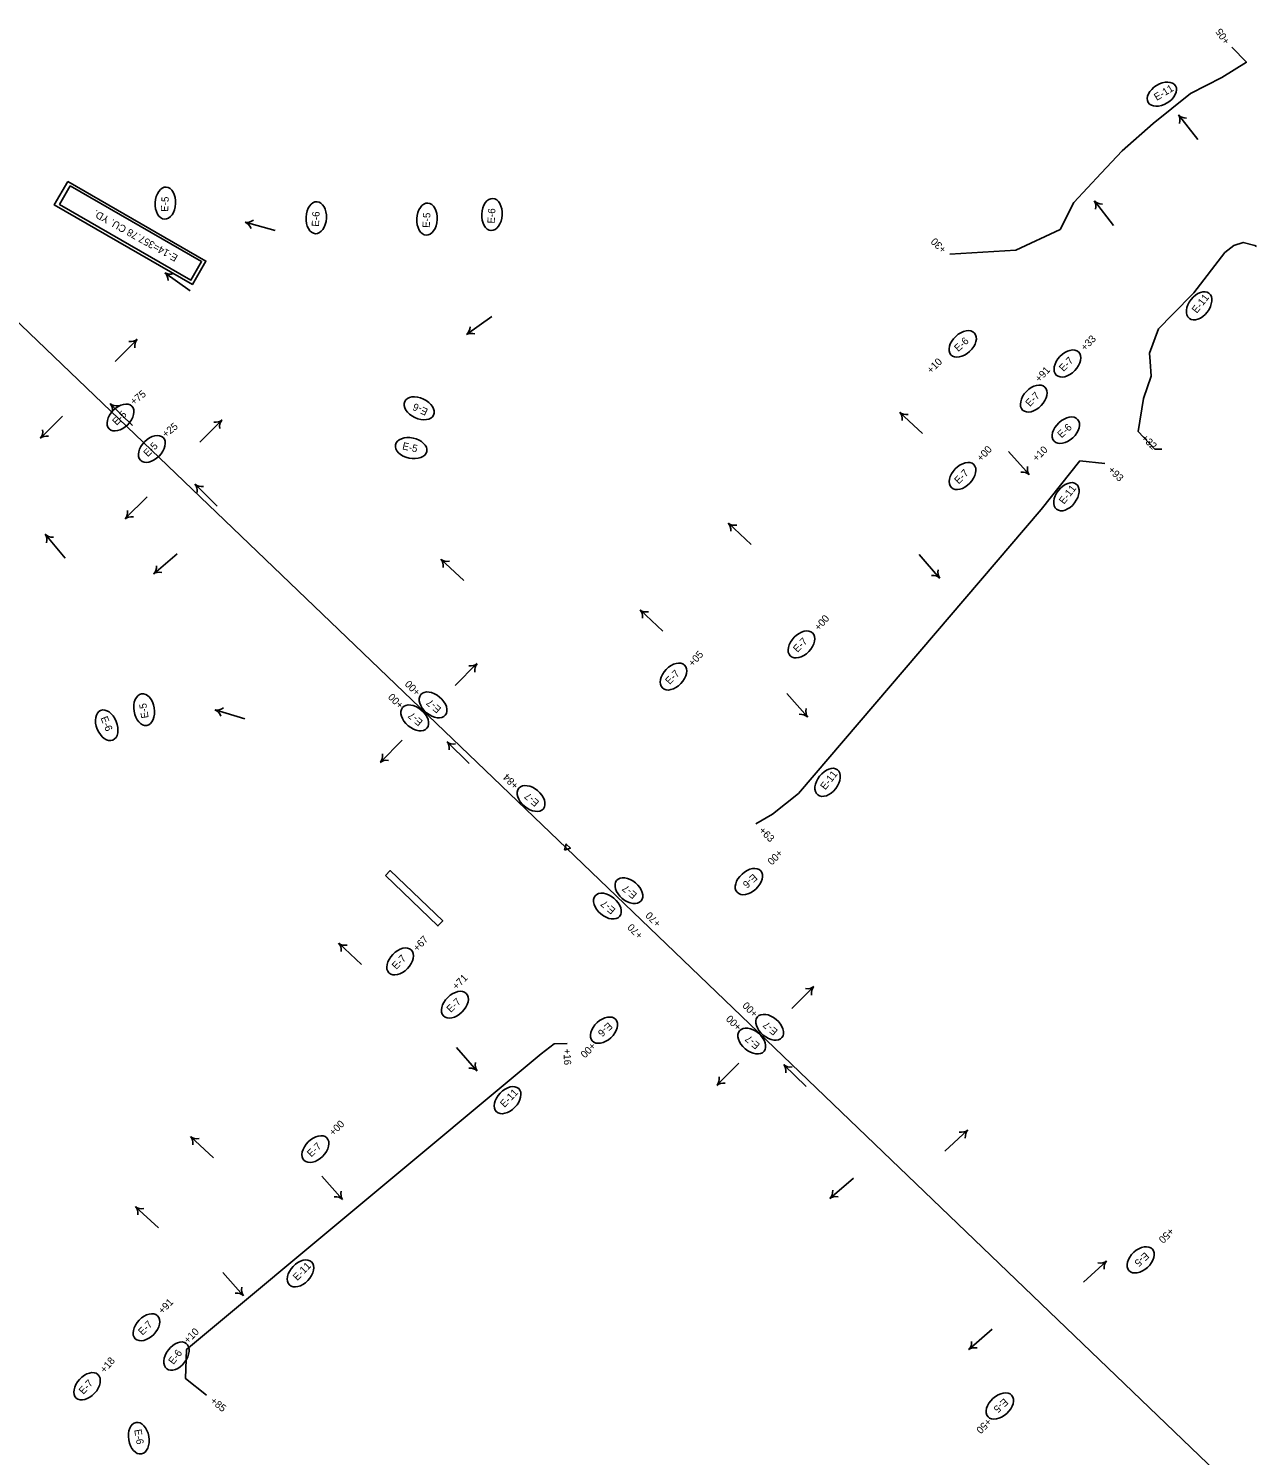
# Model space of a CAD drawing. Extents: x 669236 to 673912, y 735758 to 754788.
# Drawn here: x 671532 to 672584, y 752127 to 753348 of the extents above; entities that cross this region are included whole.
import ezdxf

# ---------------------------------------------------------------- set-up
doc = ezdxf.new("R2010")
doc.units = 0
for name, color, linetype in [('Default', 7, 'Continuous'), ('Prop_Horiz Alignment', 7, 'Continuous'), ('R_Concrete_Hatch', 7, 'Continuous'), ('R_Erosion_2', 7, 'Continuous'), ('R_Erosion_3', 7, 'Continuous'), ('R_Flow Arrows', 7, 'Continuous')]:
    doc.layers.add(name, color=color, linetype=linetype)

msp = doc.modelspace()

# ---------------------------------------------------------------- linework, layer by layer
at = {"layer": 'Default'}
for p, q in [((671992.6, 752646.7), (671411.7, 753203.9)), ((672984.6, 751695), (671992.6, 752646.7))]:
    msp.add_line(p, q, dxfattribs=at)
msp.add_lwpolyline([(672482.1, 753003.4), (672496.3, 752988.1), (672502.3, 752988.1)], dxfattribs=at)
at = {"layer": 'Prop_Horiz Alignment'}
msp.add_lwpolyline([(671990.9, 752644.9), (671992.5, 752650.2), (671996.1, 752646.7)], close=True, dxfattribs=at)
at = {"layer": 'R_Concrete_Hatch'}
msp.add_lwpolyline([(671837.7, 752623.2), (671841.9, 752627.5), (671886.8, 752584.4), (671882.6, 752580.1)], close=True, dxfattribs=at)
at = {"layer": 'R_Erosion_2'}
for centre, major_axis in [((671611, 753015.3), (9.68, 9.69)), ((671637.8, 752988.4), (9.68, 9.69)), ((671862.8, 752758.2), (-10.5, 8.8)), ((671878.5, 752769.3), (-10.5, 8.8)), ((671962.4, 752689.2), (-10.5, 8.8)), ((672046.1, 752610.3), (-10.5, 8.8)), ((672027.7, 752597.1), (-10.5, 8.8)), ((672166.6, 752493.4), (-10.5, 8.8)), ((672151.3, 752481.6), (-10.5, 8.8))]:
    msp.add_ellipse(centre, major_axis=major_axis, ratio=0.638788, dxfattribs=at)
at = {"layer": 'R_Erosion_3'}
for points in [[(672320.9, 753155.1), (672377.4, 753158.6), (672415.1, 753176.3), (672426.9, 753199.3), (672450.3, 753224.3), (672468.2, 753243.5), (672494.8, 753266.8), (672526.9, 753292.6), (672553.7, 753306.2), (672574.7, 753319.4), (672562.3, 753332.3)], [(672482.1, 753003.4), (672486.7, 753031.5), (672493, 753050.8), (672492.2, 753063.3), (672491.8, 753070.3), (672499.5, 753091.1), (672511.5, 753103.4), (672529.7, 753122.1), (672556.3, 753156.5), (672563.9, 753162.6), (672572, 753165.1), (672581.8, 753162.6), (672583.2, 753161.7)], [(672154.8, 752667.4), (672169, 752675.9), (672191.2, 752693.6), (672398.9, 752936.5), (672432.1, 752978.3), (672453.6, 752976)], [(671684.6, 752178.6), (671666.7, 752192.7), (671667.6, 752217.7), (671970.9, 752470.7), (671982.1, 752479.2), (671993.3, 752479.6)]]:
    msp.add_lwpolyline(points, dxfattribs=at)
for points in [[(671565.8, 753217.3), (671684.1, 753149.2), (671672.5, 753129.2), (671554.3, 753197.3)], [(671567.9, 753213.5), (671680.4, 753148.7), (671671.3, 753132.9), (671558.8, 753197.7)]]:
    msp.add_lwpolyline(points, close=True, dxfattribs=at)
for centre, major_axis in [((672502.3, 753292), (11.7, 7.1)), ((671649.4, 753198.8), (0.7, 13.7)), ((671778.5, 753186.3), (0.7, 13.7)), ((671873.3, 753185.1), (0.7, 13.7)), ((671928.9, 753189), (0.7, 13.7)), ((672534.2, 753110.9), (8.4, 10.8)), ((672331.8, 753078.3), (10.1, 9.3)), ((672421.4, 753061.5), (9.48, 9.88)), ((672392.6, 753031.5), (9.48, 9.88)), ((671866.6, 753023.2), (-12.4, 5.8)), ((672420.1, 753004.4), (10.1, 9.3)), ((671859.7, 752989.1), (13.4, -2.8)), ((672331.7, 752965.2), (9.54, 9.83)), ((672420.6, 752947.5), (8.4, 10.8)), ((672193.8, 752821.1), (9.54, 9.83)), ((672084.3, 752793.6), (9.54, 9.83)), ((671631.2, 752765.3), (-2.2, 13.5)), ((671599.2, 752751.9), (5.2, -12.7)), ((672216.2, 752703), (8.4, 10.8)), ((672148.8, 752618.1), (-10.1, -9.2)), ((671850.3, 752549.7), (9.54, 9.83)), ((671897.2, 752512.7), (9.77, 9.6)), ((672024.8, 752490.9), (-10.1, -9.2)), ((671942.3, 752431), (9.49, 9.87)), ((671777.8, 752389.1), (9.71, 9.66)), ((672484.1, 752294.3), (-10.1, -9.2)), ((671765, 752282.7), (9.49, 9.87)), ((671633.2, 752236.6), (9.56, 9.81)), ((671658.9, 752211.9), (8.3, 10.9)), ((671582.4, 752186.1), (9.3, 10.1)), ((672363.6, 752169.2), (-10.1, -9.2)), ((671626.6, 752141.7), (2.3, -13.5))]:
    msp.add_ellipse(centre, major_axis=major_axis, ratio=0.638788, dxfattribs=at)
at = {"layer": 'R_Flow Arrows'}
for p, q in [((672516.6, 753274.2), (672533, 753253.3)), ((672444.6, 753200.6), (672460.9, 753179.7)), ((671717.8, 753182.4), (671743.4, 753175.2)), ((671649, 753139.1), (671670.7, 753123.7)), ((671907.1, 753086.3), (671928.8, 753101.6)), ((671625.2, 753082.1), (671606.4, 753063.3)), ((671602.2, 753027.1), (671621.2, 753008.5)), ((671542.4, 752997.7), (671561.2, 753016.5)), ((672278, 753019.6), (672297.5, 753001.5)), ((671697.8, 753013), (671679, 752994.2)), ((672388.6, 752966.4), (672371, 752986.3)), ((671674.9, 752958.1), (671693.8, 752939.5)), ((671615.1, 752928.7), (671633.8, 752947.5)), ((672131.4, 752924.8), (672150.8, 752906.7)), ((671546.6, 752915.3), (671563.7, 752894.9)), ((671639.4, 752881.4), (671659.6, 752898.6)), ((671885.3, 752893.8), (671904.8, 752875.7)), ((672312.1, 752877.9), (672294.6, 752897.9)), ((672055.8, 752850.6), (672075.3, 752832.5)), ((671916.1, 752804.6), (671897.3, 752785.8)), ((672199, 752759), (672181.4, 752779)), ((671692, 752765), (671717.4, 752757.4)), ((671833.4, 752720.2), (671852.1, 752739)), ((671890.6, 752737.7), (671909.5, 752719.1)), ((671797.8, 752565.3), (671817.3, 752547.2)), ((672204.3, 752528.2), (672185.5, 752509.4)), ((671916.1, 752456.1), (671898.5, 752476)), ((672121.5, 752443.8), (672140.3, 752462.6)), ((672178.7, 752461.3), (672197.7, 752442.7)), ((672336, 752405.3), (672316.4, 752387.3)), ((671671.1, 752399.7), (671690.6, 752381.6)), ((671801, 752346.1), (671783.4, 752366)), ((672218.2, 752346.9), (672238.3, 752364.3)), ((671623.9, 752339.8), (671643.4, 752321.7)), ((671716, 752263.7), (671698.5, 752283.6)), ((672454.9, 752293.2), (672435.3, 752275.3)), ((672337, 752217.6), (672357.1, 752235))]:
    msp.add_line(p, q, dxfattribs=at)
for centre, major_axis, start_param, end_param in [((672500.4, 753262.1), (15.9, 12.4), 5.662936, 6.259934), ((672532.3, 753286.8), (-15.9, -12.4), 0.023252, 0.620249), ((672428.4, 753188.6), (15.9, 12.4), 5.662936, 6.259934), ((672460.3, 753213.3), (-15.9, -12.4), 0.023252, 0.620249), ((671711.9, 753163.1), (5.5, 19.4), 5.662936, 6.259934), ((671723, 753201.9), (-5.5, -19.4), 0.023252, 0.620249), ((671637, 753122.9), (11.7, 16.4), 5.662936, 6.259934), ((671660.5, 753155.7), (-11.7, -16.4), 0.023252, 0.620249), ((671895.3, 753102.6), (11.6, -16.5), 0.023252, 0.620249), ((671611.2, 753096.6), (14.3, -14.2), 5.662936, 6.259934), ((671639.6, 753068), (-14.3, 14.2), 0.023252, 0.620249), ((671918.4, 753069.6), (-11.6, 16.5), 5.662936, 6.259934), ((671587.8, 753013), (14.1, 14.4), 5.662936, 6.259934), ((671616.2, 753041.7), (-14.1, -14.4), 0.023252, 0.620249), ((672264, 753005.1), (13.7, 14.8), 5.662936, 6.259934), ((672291.5, 753034.5), (-13.7, -14.8), 0.023252, 0.620249), ((671528, 753011.7), (14.3, -14.2), 0.023252, 0.620249), ((671683.8, 753027.6), (14.3, -14.2), 5.662936, 6.259934), ((671712.2, 752999), (-14.3, 14.2), 0.023252, 0.620249), ((671556.4, 752983.1), (-14.3, 14.2), 5.662936, 6.259934), ((672373.6, 752952.8), (15.1, 13.3), 0.023252, 0.620249), ((672404, 752979.3), (-15.1, -13.3), 5.662936, 6.259934), ((671660.4, 752944), (14.1, 14.4), 5.662936, 6.259934), ((671688.8, 752972.7), (-14.1, -14.4), 0.023252, 0.620249), ((671629, 752914.1), (-14.3, 14.2), 5.662936, 6.259934), ((671600.6, 752942.7), (14.3, -14.2), 0.023252, 0.620249), ((672117.3, 752910.3), (13.7, 14.8), 5.662936, 6.259934), ((672144.9, 752939.7), (-13.7, -14.8), 0.023252, 0.620249), ((671530.9, 752902.7), (15.5, 12.9), 5.662936, 6.259934), ((671561.9, 752928.4), (-15.5, -12.9), 0.023252, 0.620249), ((671871.3, 752879.3), (13.7, 14.8), 5.662936, 6.259934), ((671898.8, 752908.8), (-13.7, -14.8), 0.023252, 0.620249), ((671652.1, 752865.8), (-13.1, 15.4), 5.662936, 6.259934), ((671626.1, 752896.6), (13.1, -15.4), 0.023252, 0.620249), ((672327.5, 752890.9), (-15.1, -13.3), 5.662936, 6.259934), ((672297.2, 752864.4), (15.1, 13.3), 0.023252, 0.620249), ((672041.8, 752836.1), (13.7, 14.8), 5.662936, 6.259934), ((672069.3, 752865.5), (-13.7, -14.8), 0.023252, 0.620249), ((671902.1, 752819.1), (14.3, -14.2), 5.662936, 6.259934), ((671930.6, 752790.5), (-14.3, 14.2), 0.023252, 0.620249), ((671685.8, 752745.8), (5.8, 19.3), 5.662936, 6.259934), ((671697.5, 752784.4), (-5.8, -19.3), 0.023252, 0.620249), ((672184, 752745.5), (15.1, 13.3), 0.023252, 0.620249), ((672214.4, 752772), (-15.1, -13.3), 5.662936, 6.259934), ((671876.1, 752723.6), (14.1, 14.4), 5.662936, 6.259934), ((671904.5, 752752.2), (-14.1, -14.4), 0.023252, 0.620249), ((671847.3, 752705.6), (-14.3, 14.2), 5.662936, 6.259934), ((671818.9, 752734.2), (14.3, -14.2), 0.023252, 0.620249), ((671783.8, 752550.8), (13.7, 14.8), 5.662936, 6.259934), ((671811.3, 752580.2), (-13.7, -14.8), 0.023252, 0.620249), ((672190.3, 752542.7), (14.3, -14.2), 5.662936, 6.259934), ((672218.7, 752514.1), (-14.3, 14.2), 0.023252, 0.620249), ((671901.2, 752442.6), (15.1, 13.3), 0.023252, 0.620249), ((671931.5, 752469.1), (-15.1, -13.3), 5.662936, 6.259934), ((672164.3, 752447.2), (14.1, 14.4), 5.662936, 6.259934), ((672192.7, 752475.8), (-14.1, -14.4), 0.023252, 0.620249), ((672135.5, 752429.2), (-14.3, 14.2), 5.662936, 6.259934), ((672107.1, 752457.8), (14.3, -14.2), 0.023252, 0.620249), ((672322.6, 752420.3), (13.6, -14.9), 5.662936, 6.259934), ((672350, 752390.8), (-13.6, 14.9), 0.023252, 0.620249), ((671657, 752385.2), (13.7, 14.8), 5.662936, 6.259934), ((671684.6, 752414.7), (-13.7, -14.8), 0.023252, 0.620249), ((671786, 752332.6), (15.1, 13.3), 0.023252, 0.620249), ((671816.4, 752359.1), (-15.1, -13.3), 5.662936, 6.259934), ((672231, 752331.4), (-13.2, 15.3), 5.662936, 6.259934), ((672204.8, 752362), (13.2, -15.3), 0.023252, 0.620249), ((671609.9, 752325.3), (13.7, 14.8), 5.662936, 6.259934), ((671637.4, 752354.7), (-13.7, -14.8), 0.023252, 0.620249), ((672441.4, 752308.3), (13.6, -14.9), 5.662936, 6.259934), ((672468.8, 752278.7), (-13.6, 14.9), 0.023252, 0.620249), ((671731.5, 752276.7), (-15.1, -13.3), 5.662936, 6.259934), ((671701.1, 752250.1), (15.1, 13.3), 0.023252, 0.620249), ((672323.7, 752232.7), (13.2, -15.3), 0.023252, 0.620249), ((672349.9, 752202.1), (-13.2, 15.3), 5.662936, 6.259934)]:
    msp.add_ellipse(centre, major_axis=major_axis, ratio=0.5625, start_param=start_param, end_param=end_param, dxfattribs=at)

# ---------------------------------------------------------------- texts
at = {"layer": 'R_Erosion_2'}
for s, rotation, p in [('+75', 38.8797, (671622.4, 753025.5)), ('E-5', 45.0285, (671607.6, 753008.1)), ('+25', 38.8797, (671649.7, 752997.7)), ('E-5', 45.0285, (671634.3, 752981.2)), ('+00', 134.4293, (671868.2, 752780.8)), ('+00', 134.4293, (671853.8, 752769.7)), ('E-7', 139.7558, (671886, 752766.4)), ('E-7', 139.7558, (671870.3, 752755.4)), ('+84', 134.4293, (671952.1, 752700.8)), ('E-7', 139.7558, (671969.9, 752686.4)), ('E-7', 139.7558, (672053.6, 752607.4)), ('E-7', 139.7558, (672035.2, 752594.3)), ('+70', 134.4293, (672074.1, 752582.7)), ('+70', 134.4293, (672058.6, 752572.5)), ('+00', 134.4293, (672157.1, 752505.6)), ('+00', 134.4293, (672143, 752494.2)), ('E-7', 139.7558, (672174.1, 752490.6)), ('E-7', 139.7558, (672158.8, 752478.7))]:
    msp.add_text(s, height=6.25, rotation=rotation, dxfattribs=at).set_placement(p)
at = {"layer": 'R_Erosion_3'}
for s, rotation, p in [('+05', 124.0396, (672560.9, 753337.3)), ('E-11', 31.297, (672497.9, 753286.2)), ('E-5', 87.0809, (671651.7, 753191.2)), ('E-14=357.78 CU. YD.', 150.8103, (671660.7, 753153.8)), ('E-6', 87.0809, (671780.8, 753178.5)), ('E-5', 87.0809, (671875.6, 753177.5)), ('E-6', 87.0809, (671931.2, 753181.2)), ('+30', 135.6094, (672318.4, 753159.7)), ('E-11', 51.9173, (672532.2, 753104)), ('E-6', 42.7145, (672328, 753071.2)), ('+33', 46.063, (672436.6, 753071.9)), ('+10', 45.0243, (672304.8, 753052.4)), ('E-7', 46.182, (672418.1, 753054.1)), ('+91', 47.678, (672397.6, 753045)), ('E-6', 155.0887, (671874.7, 753022.3)), ('E-7', 46.182, (672389.3, 753024.1)), ('E-6', 42.7145, (672416.3, 752997.3)), ('E-5', 348.0427, (671851.8, 752988.1)), ('+00', 46.923, (672347.7, 752977.2)), ('+10', 45.0243, (672395.1, 752977.1)), ('+32', 315.7018, (672484.2, 752997.2)), ('E-7', 45.8799, (672328.4, 752957.9)), ('+93', 315.7018, (672455.7, 752969.8)), ('E-11', 51.9173, (672418.5, 752940.6)), ('+00', 48.728, (672208.8, 752832.3)), ('E-7', 45.8799, (672190.4, 752813.8)), ('+05', 48.104, (672100.9, 752801.6)), ('E-7', 45.8799, (672081, 752786.3)), ('E-5', 99.1525, (671635.1, 752758.3)), ('E-6', 292.1065, (671593.8, 752758.1)), ('E-11', 51.9173, (672214.2, 752696.1)), ('+63', 315.7018, (672156.9, 752661.2)), ('+00', 225.0243, (672174.1, 752646.1)), ('E-6', 222.1826, (672152.6, 752625.2)), ('+67', 47.038, (671865.2, 752557.8)), ('E-7', 45.8799, (671847, 752542.4)), ('+71', 45.321, (671898.7, 752525)), ('E-7', 44.5196, (671893.7, 752505.5)), ('E-6', 222.1826, (672028.6, 752498)), ('+00', 225.0243, (672014.1, 752481)), ('+16', 271.464, (671990.2, 752475.1)), ('E-11', 46.1169, (671939.6, 752424.3)), ('+00', 44.982, (671793.2, 752400)), ('E-7', 44.8367, (671774.3, 752381.8)), ('+50', 225.0243, (672509, 752322.3)), ('E-5', 222.1826, (672487.9, 752301.3)), ('E-11', 46.1169, (671762.3, 752276)), ('+91', 46.512, (671647, 752247.4)), ('E-7', 45.717, (671629.8, 752229.3)), ('+10', 45.0243, (671668.7, 752222.2)), ('+18', 49.921, (671597.6, 752196.9)), ('E-6', 52.6862, (671656.3, 752204.2)), ('E-7', 47.4618, (671579.2, 752178.7)), ('+85', 321.2285, (671687.3, 752172.6)), ('E-5', 222.1826, (672367.3, 752176.2)), ('E-6', 279.694, (671622.7, 752148.8)), ('+50', 225.0243, (672352.9, 752159.3))]:
    msp.add_text(s, height=6.25, rotation=rotation, dxfattribs=at).set_placement(p)

doc.saveas('drawing.dxf')
